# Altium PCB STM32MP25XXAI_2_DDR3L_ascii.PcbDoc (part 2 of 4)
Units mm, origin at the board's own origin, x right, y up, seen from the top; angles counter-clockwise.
Board outline 172 x 137 mm, 6 copper layers (Top Layer, Signal Layer 1, Signal Layer 2, Signal Layer 3, Signal Layer 4, Bottom Layer), stack 2.079 mm thick; 237 components, 152 nets, 1304 pads, 909 vias.
Unrouted connection lines stored in the file: 13.
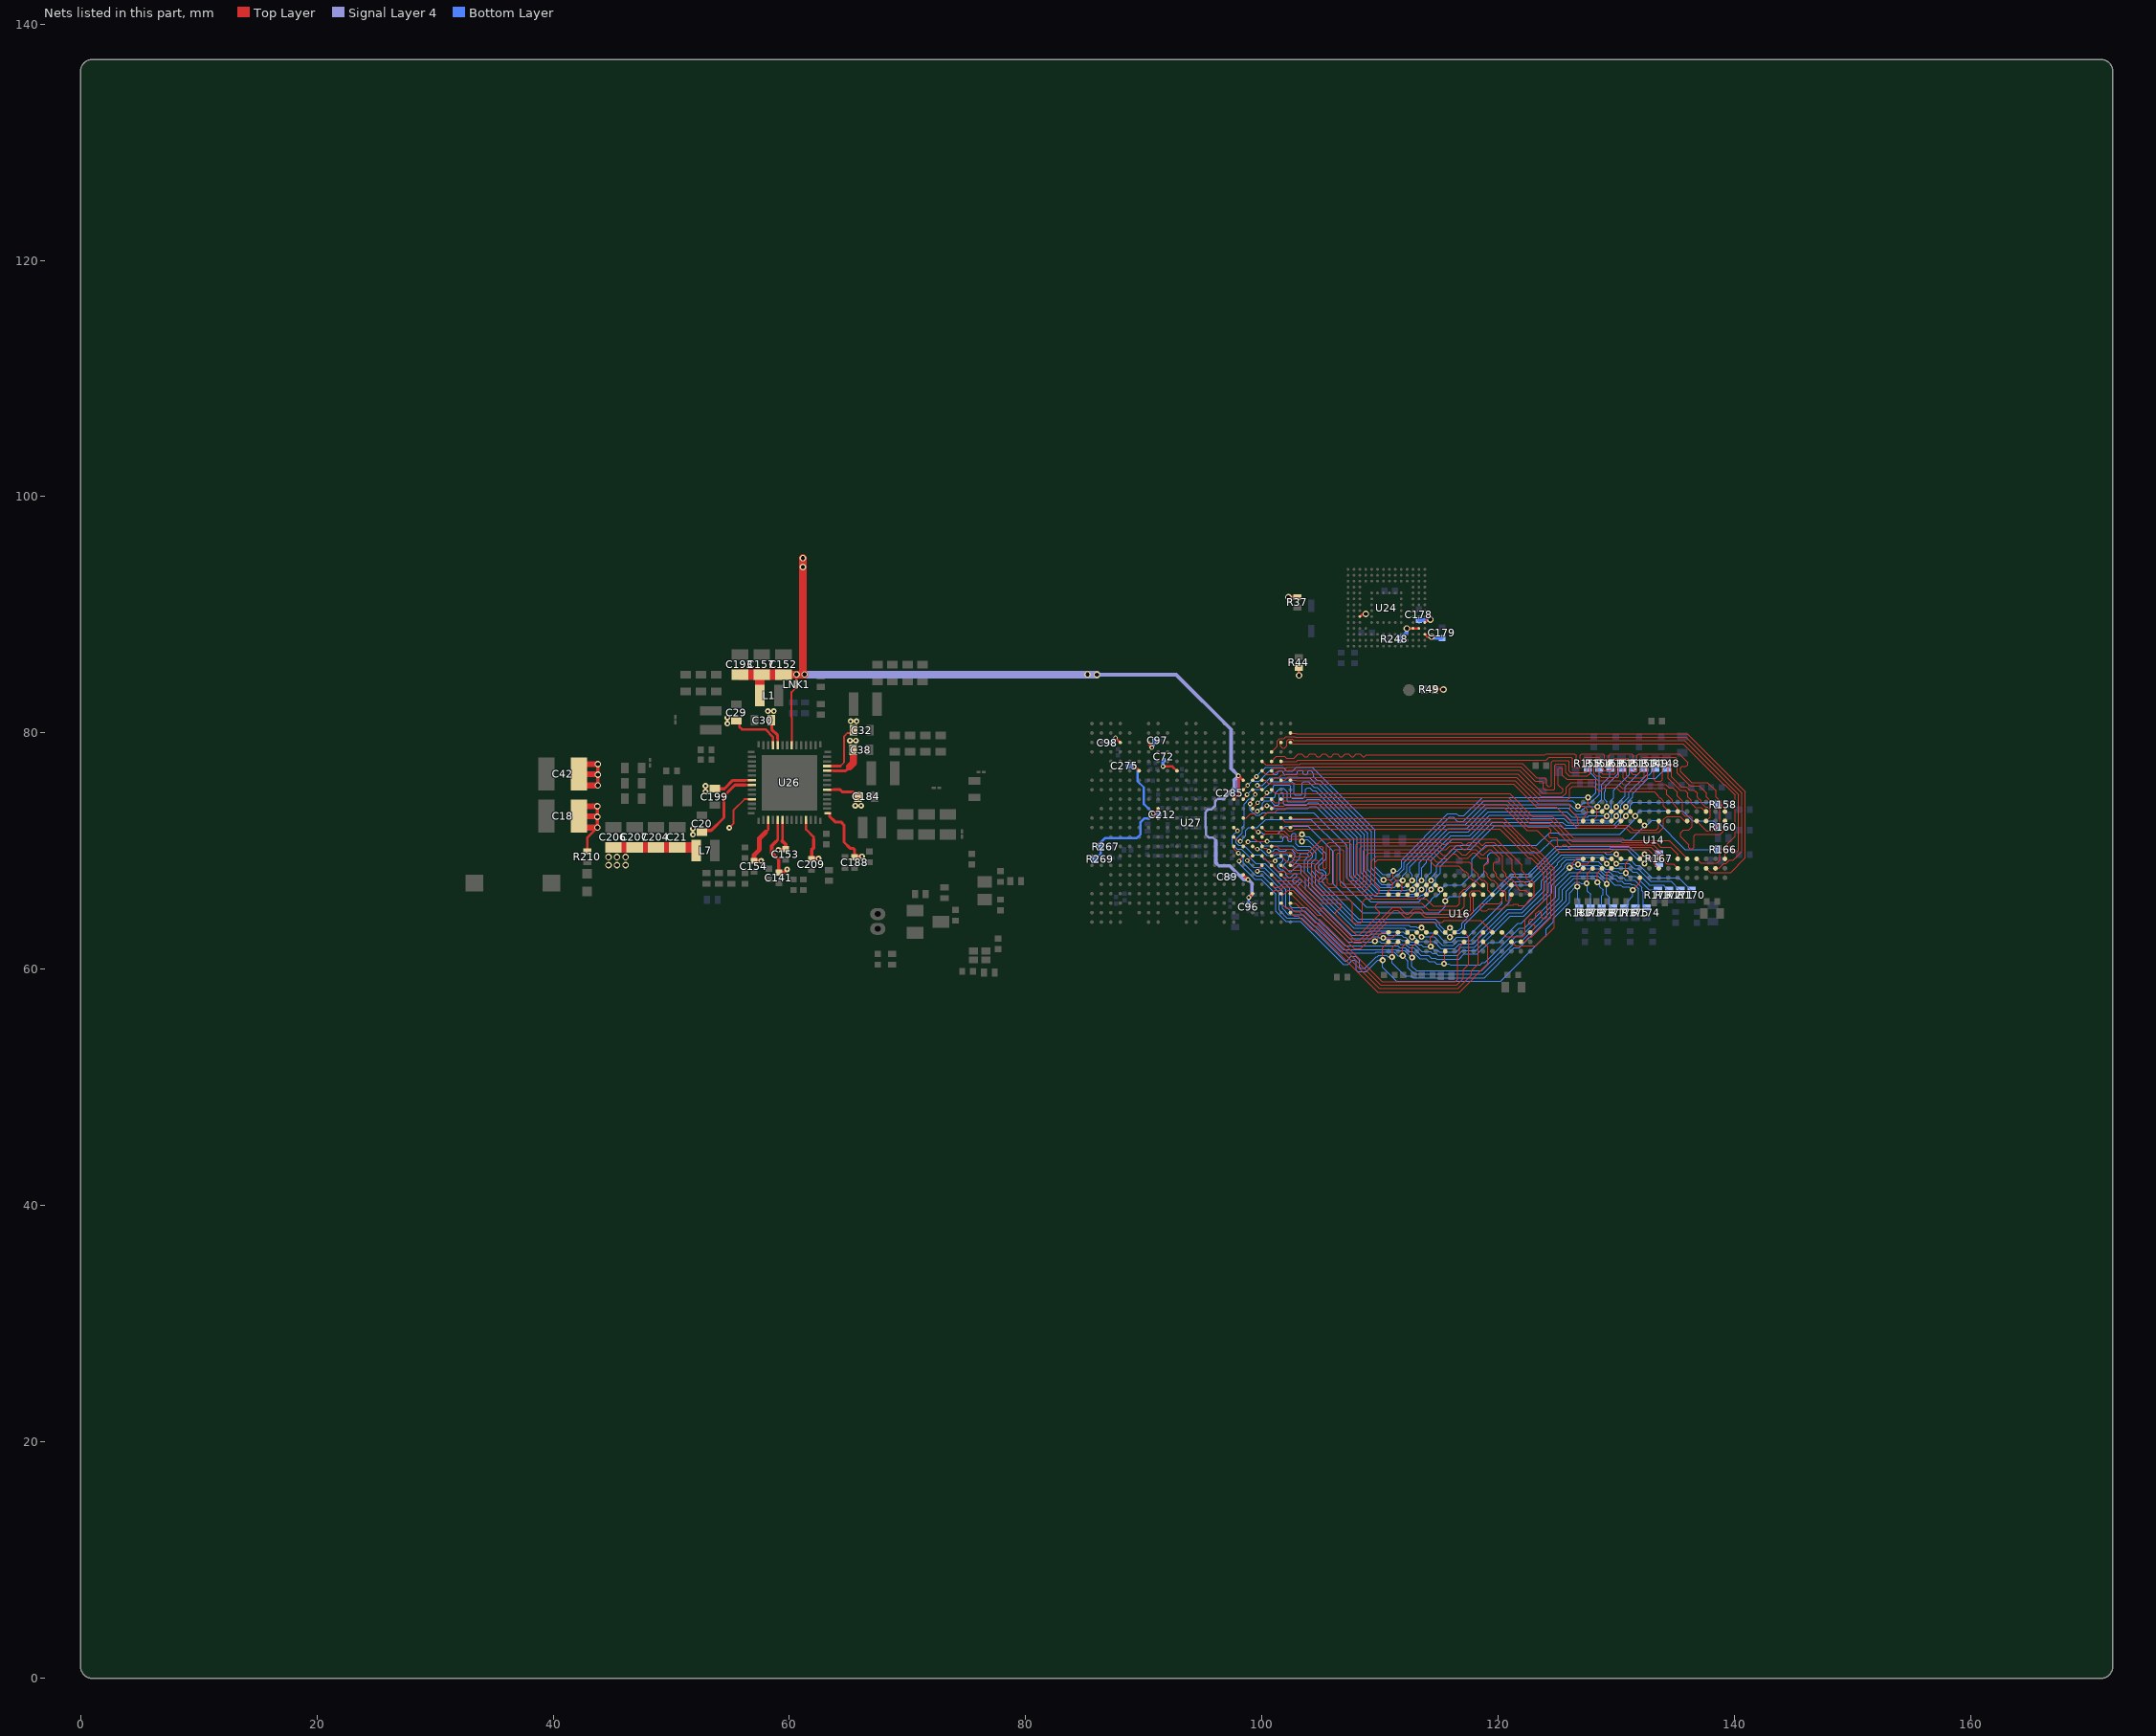
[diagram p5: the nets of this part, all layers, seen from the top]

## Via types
v1: diameter 0.55, hole 0.35, Top Layer to Bottom Layer, 421 vias
v2: diameter 0.4, hole 0.2, Top Layer to Bottom Layer, tented both sides, 169 vias
v3: diameter 0.5, hole 0.2, Top Layer to Bottom Layer, 146 vias
v4: diameter 0.5, hole 0.25, Top Layer to Bottom Layer, 145 vias
v5: diameter 0.4, hole 0.2, Top Layer to Bottom Layer, 28 vias

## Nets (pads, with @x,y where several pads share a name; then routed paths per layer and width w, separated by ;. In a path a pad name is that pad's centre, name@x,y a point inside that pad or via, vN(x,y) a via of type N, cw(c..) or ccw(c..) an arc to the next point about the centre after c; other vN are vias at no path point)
1V8: C72.2 C89.2 C96.2 C97.2 C98.2 C152.2 C157.2 C178.2 C179.2 C193.2 C212.2 C275.2 C285.2 L1.2 LNK1.2 R37.2 R44.2 R49.2 R248.2 R267.2 R269.1 U24.C6 U24.M4 U24.N4 U24.P3 U24.P5 U27.C4 U27.C7 U27.F6 U27.F10 U27.G17 U27.J16 U27.K8 U27.L8 U27.U17 U27.W18 | length 110.6
  Top Layer w0.2: LNK1.2@60.6,84.348 v1(60.6,84.95) ; v2(87.6,79.6) U27.C4@88,79.2 v2(87.6,79.6) ; v2(89.2,77.2) U27.F6@89.6,76.8 ; U27.C7@90.4,79.2 90.415,79.185 90.415,79.02 v2(90.66,78.775) ; U27.L8@91.2,72.8 91.175,72.8 v2(90.8,73.175) 91.2,73.575 U27.K8@91.2,73.6 ; v2(91.624,77.173) 92.413,77.173 92.786,76.8 U27.F10@92.8,76.8 ; U27.J16@97.6,74.4 98,74.8 v2(98,76.375) 98.012,76.375 98.388,76 U27.G17@98.4,76 ; U27.U17@98.4,68 v2(98.8,67.6) ; v2(98.868,66.067) U27.W18@99.2,66.4 ; v1(102.23,91.5) R37.2@102.975,91.5 ; R44.2@103.1,85.528 103.125,85.503 v1(103.125,84.875) ; U24.C6@108.275,89.85 108.452,90.027 108.727,90.027 v1(108.775,90.075) ; v1(112.25,88.85) U24.M4@112.775,88.85 U24.N4@113.275,88.85 ; U24.P3@113.775,88.35 113.975,88.15 v1(114.35,88.15) ; U24.P5@113.775,89.35 114.005,89.58 114.23,89.58 v1(114.25,89.6) ; R49.2@114.625,83.685 v1(115.35,83.685)
  Top Layer w0.64: C152.2@59.5,84.95 v1(60.6,84.95) v1(61.28,84.95) 61.142,85.088 v1(61.142,94.8)
  Top Layer w0.8: L1.2@57.495,83.175 57.495,84.9 57.545,84.95 C157.2@57.65,84.95
  Top Layer w0.9: C193.2@55.8,84.95 C157.2@57.545,84.95 ; C157.2@57.65,84.95 C152.2@59.5,84.95
  Signal Layer 4 w0.2: 96.075,70.9 95.825,71.15 95.484,71.15 95.399,71.235 95.248,71.386 95.248,72.063 95.201,72.109 95.201,73.292 95.317,73.408 95.317,73.433 95.434,73.55 95.723,73.55 96.007,73.834 96.007,74.166 96.003,74.169 96.257,74.423 96.684,74.423 ; v2(98.868,66.067) v2@98.868,66.094
  Signal Layer 4 w0.3: v1(86.019,84.939) 92.721,84.939 97.371,80.289 97.371,77.004 v2(98,76.375) ; 96.075,70.9 96.075,69.048 96.075,69.014 96.339,68.75 97.262,68.75 98.412,67.6 v2(98.8,67.6) ; 96.684,74.423 97.65,75.389 97.65,76.018 v2@98,76.367 ; v2(98.8,67.6) 99.15,67.25 99.15,66.377 v2@98.868,66.094
  Signal Layer 4 w0.64: v1@60.6,84.955 v1@61.28,84.955 ; v1(61.28,84.95) 86.009,84.95 v1(86.019,84.939)
  Bottom Layer w0.17: C89.2@97.35,67.825 97.415,67.89 97.44,67.89 97.56,68.01 98.39,68.01 v2(98.8,67.6)
  Bottom Layer w0.2: R269.1@85.854,69.315 85.854,69.41 86.009,69.565 86.104,69.565 86.35,69.811 R267.2@86.35,70.375 ; R267.2@86.325,70.715 86.697,71.087 89.377,71.087 89.723,71.434 89.723,72.448 90.059,72.783 90.457,72.783 90.8,73.127 v2(90.8,73.175) ; v2(89.2,77.2) 89.458,76.942 89.458,75.927 89.985,75.4 89.985,73.99 v2(90.8,73.175) ; v2(90.66,78.775) 90.66,78.79 90.825,78.955 C97.2@90.825,79.375 ; C212.2@91.31,73.1 91.272,73.138 90.837,73.138 v2(90.8,73.175) ; C96.2@98.85,65.55 98.85,66.05 v2(98.868,66.067)
  Bottom Layer w0.3: C98.2@87.175,79.175 v2(87.6,79.6) ; C72.2@91.6,77.7 91.6,77.224 91.624,77.2 v2(91.624,77.173) ; C285.2@97.555,74.91 97.94,75.295 97.94,76.288 98,76.348 v2(98,76.375) ; R248.2@111.675,87.95 112.241,88.516 112.241,88.841 v1(112.25,88.85) ; C178.2@113.275,89.55 114.132,89.55 114.182,89.6 v1(114.25,89.6) ; v1(114.35,88.15) 114.418,88.15 114.543,88.025 C179.2@115.225,88.025
  Bottom Layer w0.4: C275.2@88.675,77.2 v2(89.2,77.2)
  other v1: 85.224,84.95 61.131,94.047
1V8_FB: LNK1.1 U26.35 | length 5.1
  Top Layer w0.15: U26.35@60.2,78.97 60.2,81.311 60.175,81.336 60.175,83.473 LNK1.1@60.6,83.898
3V3: C21.2 C154.2 C204.2 C206.2 C207.2 L7.2 U26.3 U26.53 | length 15.3
  Top Layer w0.15: v3(54.91,71.977) 55.262,72.329 55.262,73.465 56.197,74.4 U26.53@56.83,74.4 ; U26.53@56.62,74.369 56.919,74.369 U26.53@56.95,74.4
  Top Layer w0.21: 57.973,71.598 58.2,71.825 U26.3@58.2,72.63
  Top Layer w0.3: C154.2@56.975,69.175 C154.2@57,69.175 v3@57.585,69.175
  Top Layer w0.4: C154.2@57,69.175 57.014,69.189 57.014,69.685 57.46,70.131 57.46,71.085 57.973,71.598
  Top Layer w0.9: C206.2@45.087,70.323 C21.2@50.5,70.323 51.862,70.323 L7.2@51.887,70.298
  other v1: 44.687,68.823 45.412,68.823 46.137,68.823 44.687,69.498 45.412,69.498 46.137,69.498
  other v3: 57.61,69.175
5V_STLK: C18.1 C20.2 C29.2 C30.2 C32.2 C38.2 C42.1 C153.2 C184.2 C188.2 C199.2 C209.2 R210.1 U26.6 U26.11 U26.15 U26.20 U26.24 U26.25 U26.38 U26.39 U26.49 U26.50 | length 56.5
  Top Layer w0.15: 64.3,77.2 64.625,77.525 64.625,79.731 64.888,79.994 65.319,79.994 C32.2@65.425,80.1
  Top Layer w0.2: R210.1@42.887,69.97 42.887,71.138 v1(43.751,72.002)
  Top Layer w0.21: C29.2@55.525,81.05 55.762,80.813 55.762,80.513 55.975,80.3 57.964,80.3 58.6,79.664 U26.39@58.6,78.97 ; 56.275,75.6 U26.50@56.83,75.6 ; 56.275,76 U26.49@56.83,76 ; U26.38@59,78.97 59,79.525 ; 59.4,70.85 U26.6@59.4,72.63 ; U26.11@61.4,72.63 61.4,71.843 62.04,71.203 62.04,70.975 ; U26.15@63.17,73.2 U26.15@63.245,73.2 U26.15@63.285,73.2 ; U26.20@63.17,75.2 63.725,75.2 ; U26.24@63.17,76.8 63.725,76.8 ; U26.25@63.17,77.2 64.3,77.2
  Top Layer w0.25: C20.2@52.6,71.75 53.375,71.75 54.45,72.825 54.45,74.669 55.381,75.6 56.275,75.6 ; C199.2@53.675,75.275 54.491,75.275 55.216,76 56.275,76 ; C30.2@58.425,81.075 58.494,81.006 58.494,80.308 59,79.802 59,79.525 ; 63.395,73.095 63.395,72.947 63.871,72.472 64.353,72.472 64.625,72.2 64.625,70.759 65.134,70.25 65.379,70.25 65.525,70.104 C188.2@65.525,69.55 ; 63.725,75.2 64.288,75.2 64.463,75.025 65.347,75.025 65.472,74.9 65.55,74.9 65.747,74.703 C184.2@65.747,74.625 ; 63.725,76.8 64.75,76.8 65.075,77.125
  Top Layer w0.3: v1(43.751,72.002) v1(43.751,72.902) v1(43.751,73.802) ; v1(43.776,75.565) v1(43.776,76.465) v1(43.776,77.365) ; v3(59.065,70.11) 59.675,70.11 59.674,70.111 59.674,70.576 59.4,70.85 ; C209.2@61.85,69.38 C209.2@61.875,69.38 ; 62.04,70.975 62.04,70.269 61.875,70.104 C209.2@61.875,69.38 ; v3(62.46,69.38) C209.2@61.875,69.38 ; C188.2@65.525,69.55 v3(66.135,69.55)
  Top Layer w0.5: C18.1@42.187,72.049 42.235,72.002 v1(43.751,72.002) ; C18.1@42.187,72.961 43.679,72.961 43.737,72.902 v1(43.751,72.902) ; C42.1@42.187,75.612 42.235,75.565 v1(43.776,75.565) ; C42.1@42.187,76.523 43.704,76.523 43.762,76.465 v1(43.776,76.465) ; C18.1@42.246,73.802 v1(43.751,73.802) ; C42.1@42.246,77.365 v1(43.776,77.365)
  Top Layer w0.6: 65.075,77.125 65.4,77.45 C38.2@65.4,78.175
  other v3: 51.825,71.4 51.825,71.9 65.575,73.85 66.075,73.85 52.9,75.025 52.9,75.525 65.125,79.35 65.625,79.35 54.75,80.8 65.175,81 65.675,81 54.75,81.3 58.175,81.85 58.675,81.85
5V_VCONN: C141.1 U26.5 | length 5.7
  Top Layer w0.21: 58.877,70.828 59,70.95 U26.5@59,72.63
  Top Layer w0.3: 58.877,70.828 58.51,70.46 58.51,69.865 59.1,69.275 C141.1@59.1,68.2 59.539,68.2 v3(59.8,68.46)
DDR_A0: R149.1 U14.N3 U16.N3 U27.L17 | length 50.4
  Top Layer w0.09: U27.L17@98.4,72.8 98.673,72.8 99.037,73.164 99.374,73.164 v5(99.6,73.39) ; U16.N3@113.101,66.327 113.101,66.376 v4@113.5,66.775 ; U14.N3@129.576,72.552 129.576,72.601 v4@129.975,73
  Bottom Layer w0.09: v5@99.603,73.39 100.016,73.803 100.016,74.043 100.219,74.246 100.712,74.246 101.058,73.9 101.348,73.9 101.443,73.995 101.443,74.811 101.603,74.971 101.748,74.971 101.833,74.886 101.833,74.017 101.95,73.9 103.774,73.9 103.962,74.088 104.682,74.088 105.043,73.727 ; 105.05,73.734 107.755,71.029 107.755,67.967 109.502,66.22 112.251,66.22 112.32,66.151 112.967,66.151 113.5,66.685 v4(113.5,66.745) 113.5,66.818 113.715,67.033 113.715,67.097 113.895,67.277 113.895,67.808 114.336,68.25 114.336,69.245 116.116,71.025 117.679,71.025 119.404,72.75 125.544,72.75 125.912,72.382 129.422,72.382 129.975,72.935 v4(129.975,72.97) v4@129.975,73 ; v4@129.976,73.013 129.976,73.139 130.37,73.534 130.37,73.908 131.064,74.602 131.064,74.979 132.537,76.452 132.751,76.452 132.971,76.672 132.971,76.767 133.181,76.977 R149.1@133.276,76.977
DDR_A1: R172.1 U14.P7 U16.P7 U27.P19 | length 48.6
  Top Layer w0.09: U27.P19@100.005,70.4 100.168,70.237 100.338,70.237 v5(100.575,70) ; U16.P7@112.301,63.127 v4(112.7,62.725) ; U14.P7@128.776,69.352 v4@129.176,68.952
  Bottom Layer w0.09: v5(100.575,70) 100.585,69.99 100.909,69.99 101.096,70.177 101.282,70.177 101.432,70.027 101.968,70.027 102.118,70.177 102.453,70.177 102.802,69.827 102.802,69.539 102.652,69.388 102.652,69.283 102.349,68.98 102.349,68.846 102.424,68.772 102.566,68.772 103.197,69.402 103.197,69.689 103.327,69.82 103.784,69.82 103.903,69.7 103.903,69.576 103.586,69.258 103.586,68.134 103.953,67.766 103.953,66.903 107.68,63.177 109.148,63.177 109.231,63.26 110.6,63.26 110.683,63.177 111.946,63.177 112.101,63.022 112.406,63.022 v4@112.672,62.756 ; v4@112.685,62.769 112.7,62.754 112.7,62.728 v4(112.7,62.725) 112.763,62.662 113.002,62.662 113.32,62.344 114.55,62.344 115.145,61.75 116.304,61.75 116.711,62.157 117.833,62.157 120.761,65.085 121.919,65.085 123.64,66.806 123.64,67.493 125.03,68.884 125.03,68.984 125.538,69.492 128.592,69.492 129.134,68.95 v4(129.175,68.95) 129.175,68.931 129.439,68.667 129.669,68.667 129.782,68.554 131.028,68.554 131.372,68.211 131.69,68.211 132.659,67.242 132.673,67.242 132.765,67.15 133.959,67.15 134.145,66.964 134.145,66.905 R172.1@134.45,66.6
DDR_A2: R151.1 U14.P3 U16.P3 U27.J19 | length 47.1
  Top Layer w0.09: U27.J19@100,74.4 100,74.438 100.341,74.779 100.341,74.891 v5(100.4,74.95) ; U16.P3@112.301,66.327 112.7,66.726 v4(112.7,66.745) ; U14.P3@128.776,72.552 129.175,72.951 v4(129.175,72.97)
  Bottom Layer w0.09: v5@100.403,74.95 100.747,74.95 100.95,75.153 100.95,75.501 101.051,75.602 102.305,75.602 102.413,75.494 102.413,74.594 102.527,74.48 103.461,74.48 103.689,74.708 103.689,75.224 103.824,75.359 104.044,75.359 104.287,75.115 104.517,75.115 108.355,71.278 108.355,68.187 109.842,66.7 112.213,66.7 112.258,66.745 v4(112.7,66.745) 112.778,66.823 112.778,67.042 113.095,67.358 113.095,67.845 113.168,67.918 113.168,67.92 113.3,68.052 113.3,69.057 ; 113.299,69.057 115.867,71.625 117.43,71.625 119.155,73.35 125.793,73.35 126.241,72.902 127.573,72.902 127.668,72.997 v4@129.172,72.997 ; v4(129.175,72.97) 129.175,73.095 129.57,73.49 129.57,74.31 129.765,74.505 129.765,75.167 131.071,76.472 131.071,76.767 131.281,76.977 R151.1@131.376,76.977
DDR_A3: R150.1 U14.N2 U16.N2 U27.K18 | length 47.8
  Top Layer w0.09: U27.K18@99.2,73.6 99.2,73.65 v5@99.625,74.075 ; U16.N2@113.101,67.127 113.476,67.502 v4@113.476,67.527 ; U14.N2@129.575,73.35 v4(129.975,73.75)
  Bottom Layer w0.09: v5@99.625,74.063 100.109,74.546 101.03,74.546 101.14,74.656 101.14,74.918 101.524,75.302 101.828,75.302 102.123,75.007 102.123,74.238 102.171,74.19 103.654,74.19 103.842,74.378 104.83,74.378 108.055,71.153 108.055,68.077 109.672,66.46 112.315,66.46 112.425,66.35 112.864,66.35 113.095,66.581 113.095,66.899 113.31,67.114 113.31,67.267 113.5,67.457 v4(113.5,67.525) 113.505,67.53 113.505,68.614 113.916,69.025 113.916,69.249 115.992,71.325 117.554,71.325 119.279,73.05 125.669,73.05 126.075,72.644 128.943,72.644 129.011,72.575 129.339,72.575 129.58,72.816 129.58,73.164 129.897,73.48 129.897,73.672 v4(129.975,73.75) ; v4@130.018,73.956 130.712,74.651 130.712,75.438 132.021,76.746 132.021,76.767 132.231,76.977 R150.1@132.326,76.977
  other v5: 99.625,74.1
DDR_A4: R178.1 U14.P8 U16.P8 U27.T19 | length 43.4
  Top Layer w0.09: v5(99.6,68.3) 99.6,68.302 99.798,68.501 99.798,68.591 U27.T19@100,68.793 ; v4(111.9,61.145) 111.901,61.927 U16.P8@112.301,62.327 ; v4(128.375,67.35) 128.376,68.152 U14.P8@128.776,68.552
  Bottom Layer w0.09: v5(99.6,68.3) 100.063,68.3 101.734,66.629 101.734,65.145 102.237,64.642 103.471,64.642 106.736,61.377 109.575,61.377 109.65,61.452 111.181,61.452 111.488,61.145 v4(111.9,61.145) 112.36,60.685 112.36,60.134 112.904,59.59 118.694,59.59 121.482,62.378 121.92,62.378 125.44,65.898 125.44,66.748 126.377,67.685 128.101,67.685 128.375,67.411 v4(128.375,67.35) 128.375,67.34 128.573,67.142 128.573,66.992 128.846,66.72 128.846,66.347 128.743,66.244 128.743,65.232 R178.1@128.75,65.225
DDR_A5: R152.1 U14.P2 U16.P2 U27.J17 | length 48.4
  Top Layer w0.09: U27.J17@98.4,74.4 98.4,74.438 98.725,74.763 v5(98.725,74.775) ; U16.P2@112.302,67.127 v4(112.7,67.525) ; U14.P2@128.776,73.352 128.777,73.352 v4(129.175,73.75)
  Bottom Layer w0.09: v5(98.725,74.775) 99.174,75.224 100.113,75.224 100.791,75.902 102.504,75.902 102.703,75.703 102.703,74.866 102.799,74.77 103.304,74.77 103.399,74.865 103.399,75.763 103.538,75.902 103.924,75.902 104.411,75.415 104.642,75.415 108.655,71.402 108.655,68.297 108.918,68.034 110.012,66.94 111.189,66.94 111.438,67.189 111.613,67.189 111.701,67.102 ; 111.699,67.1 111.859,66.94 112.029,66.94 112.216,67.127 112.302,67.127 v4(112.7,67.525) 112.7,68.005 112.487,68.218 112.487,68.669 115.743,71.925 117.306,71.925 119.031,73.65 125.917,73.65 126.425,73.142 127.3,73.142 127.503,73.345 128.644,73.345 129.049,73.75 v4(129.175,73.75) 129.191,73.766 129.191,74.172 128.972,74.391 128.972,75.001 129.076,75.105 129.076,75.477 130.121,76.522 130.121,76.767 130.331,76.977 R152.1@130.426,76.977
DDR_A6: R179.1 U14.R8 U16.R8 U27.P16 | length 46.7
  Top Layer w0.09: U27.P16@97.6,70.4 97.624,70.376 97.624,70.155 97.934,69.845 v5(98,69.845) ; v4(111,61.05) 111.047,61.096 111.047,61.872 U16.R8@111.5,62.325 ; v4(127.475,67.275) 127.523,67.323 127.523,68.09 127.976,68.542 U14.R8@127.976,68.552
  Bottom Layer w0.09: v5(98,69.845) 98.4,69.445 98.4,69.012 99.492,67.92 100.025,67.92 101.444,66.5 101.444,65.025 102.117,64.352 103.351,64.352 106.991,60.712 107.147,60.712 107.522,61.087 107.928,61.087 108.242,60.772 108.242,60.182 108.344,60.081 108.688,60.081 109.684,61.077 109.759,61.077 109.854,61.172 110.514,61.172 110.636,61.05 v4(111,61.05) 111,60.516 112.08,59.436 112.648,59.436 112.784,59.3 118.814,59.3 121.338,61.824 121.776,61.824 125.74,65.788 125.74,66.623 126.511,67.395 126.839,67.395 126.985,67.248 127.449,67.248 v4(127.475,67.275) 127.52,67.23 127.52,66.63 127.801,66.349 R179.1@127.801,65.227
DDR_A7: R155.1 U14.R2 U16.R2 U27.G18 | length 43.8
  Top Layer w0.09: U27.G18@99.2,76 v5(99.525,76.325) ; v4(111.1,68.325) 111.1,67.772 111.447,67.425 111.447,67.178 U16.R2@111.5,67.125 ; v4(127.575,74.55) 127.575,73.997 127.969,73.603 127.969,73.356 U14.R2@127.975,73.35
  Bottom Layer w0.09: v5(99.525,76.325) 100.302,77.102 101.791,77.102 102.111,76.782 102.594,76.782 102.914,77.102 104.228,77.102 109.555,71.775 109.555,68.67 110.187,68.038 110.81,68.038 111.097,68.325 v4(111.1,68.325) 111.505,68.325 111.8,68.62 111.8,69.255 115.72,73.175 116.432,73.175 116.616,72.991 117.099,72.991 118.658,74.55 v4(127.575,74.55) 127.615,74.59 127.9,74.59 128.249,74.938 128.249,76.156 127.767,76.638 127.767,76.786 R155.1@127.576,76.977
DDR_A8: R180.1 U14.T8 U16.T8 U27.R17 | length 45.9
  Top Layer w0.09: v5(98.05,69.15) 98.05,69.216 98.4,69.566 U27.R17@98.4,69.6 ; v4(110.2,60.775) 110.2,61.826 U16.T8@110.701,62.327 ; v4(126.675,67) 126.675,68.051 U14.T8@127.176,68.552
  Bottom Layer w0.09: v5@98.05,69.175 98.109,69.116 98.109,68.893 99.372,67.63 99.905,67.63 101.154,66.38 101.154,64.905 101.997,64.062 103.231,64.062 106.871,60.422 107.268,60.422 107.643,60.797 107.808,60.797 107.952,60.652 107.952,59.919 108.08,59.791 108.808,59.791 109.794,60.777 v4@110.2,60.777 ; v4(110.2,60.775) 110.2,60.189 111.379,59.01 120.203,59.01 124.063,62.871 124.063,63.411 124.67,64.017 124.67,64.308 126.03,65.668 126.03,66.458 126.571,67 v4(126.675,67) v4@126.675,66.903 ; v4@126.678,66.903 126.73,66.852 126.73,65.909 126.851,65.788 R180.1@126.851,65.227
DDR_A9: R153.1 U14.R3 U16.R3 U27.H19 | length 45.3
  Top Layer w0.09: v5(99.6,75.575) 99.625,75.575 U27.H19@100,75.2 ; U16.R3@111.501,66.327 111.876,66.702 v4@111.876,67.502 ; U14.R3@127.976,72.552 128.351,72.927 v4@128.351,73.727
  Bottom Layer w0.09: v5@99.605,75.57 100.038,75.57 100.67,76.202 104.049,76.202 104.536,75.715 104.766,75.715 108.955,71.526 108.955,68.421 109.88,67.496 109.88,67.404 110.104,67.18 111.005,67.18 111.351,67.526 v4@111.899,67.526 ; v4(111.9,67.525) 111.9,67.921 112.25,68.271 112.25,68.856 115.619,72.225 117.182,72.225 118.907,73.95 126.041,73.95 126.586,73.405 127.017,73.405 127.389,73.777 128.351,73.777 128.417,73.843 128.417,74.073 128.745,74.401 128.745,75.631 129.442,76.327 129.442,76.943 R153.1@129.476,76.977
  other v4: 128.375,73.75
DDR_A10: R173.1 U14.L7 U16.L7 U27.P18 | length 48.2
  Top Layer w0.09: U27.P18@99.2,70.4 99.254,70.4 99.42,70.234 99.541,70.234 v5(99.6,70.175) ; v4@114.256,61.931 114.256,62.681 U16.L7@114.7,63.125 ; v4(130.775,68.15) 130.775,68.95 U14.L7@131.175,69.35
  Bottom Layer w0.09: v5(99.6,70.175) 99.642,70.133 99.913,70.133 100.409,69.637 101.112,69.637 101.202,69.727 102.095,69.727 102.247,69.575 102.247,69.288 101.84,68.881 101.84,68.724 102.309,68.255 102.477,68.255 103.053,68.83 103.182,68.83 103.296,68.716 103.296,68.014 103.663,67.646 103.663,66.783 107.56,62.887 109.163,62.887 109.296,63.02 110.086,63.02 110.111,63.045 110.51,63.045 110.581,62.974 ; 110.582,62.974 110.679,62.877 111.822,62.877 111.977,62.722 112.14,62.722 112.52,62.342 112.524,62.342 112.536,62.33 113.013,62.33 113.266,62.077 113.47,62.077 113.623,61.924 v4@114.279,61.924 ; 115.024,61.46 115.013,61.46 114.833,61.64 114.561,61.64 114.561,61.644 v4(114.28,61.925) ; 115.024,61.46 116.424,61.46 116.831,61.867 117.968,61.867 120.886,64.785 122.029,64.785 123.94,66.696 123.94,67.369 125.33,68.759 125.33,68.874 125.726,69.27 126.921,69.27 127.081,69.109 128.45,69.109 129.082,68.477 129.496,68.477 129.667,68.305 129.862,68.305 129.913,68.254 130.13,68.254 130.234,68.15 v4(130.775,68.15) 130.775,68.125 131.025,67.875 131.615,67.875 132.741,66.75 R173.1@133.5,66.75 ; v4@114.279,61.924 v4(114.28,61.925)
DDR_A11: R174.1 U14.R7 U16.R7 U27.R19 | length 48.7
  Top Layer w0.09: U27.R19@100,69.6 100.42,69.18 v5(101.105,69.18) ; v4(110.25,62.65) 110.27,62.67 111.045,62.67 U16.R7@111.5,63.125 ; v4(126.725,68.875) 126.751,68.901 127.525,68.901 U14.R7@127.976,69.352
  Bottom Layer w0.09: v5(101.105,69.18) 101.105,69.206 101.326,69.427 101.686,69.427 101.769,69.344 101.769,69.22 101.331,68.782 101.331,68.672 101.585,68.418 101.736,68.418 102.012,68.142 102.012,67.992 102.25,67.754 102.393,67.754 102.762,68.123 102.876,68.123 102.961,68.038 102.961,67.903 102.596,67.538 102.596,67.408 102.693,67.31 102.83,67.31 103.147,67.628 103.271,67.628 103.366,67.533 103.366,67.409 103.047,67.09 103.047,66.956 107.406,62.597 109.212,62.597 109.368,62.753 109.37,62.753 109.386,62.77 109.822,62.77 109.943,62.649 v4(110.25,62.65) 110.3,62.65 v4@110.355,62.595 ; v4@110.401,62.577 111.698,62.577 111.853,62.422 112.143,62.422 112.506,62.059 112.947,62.059 113.501,61.505 114.254,61.505 114.409,61.35 114.713,61.35 114.893,61.17 114.904,61.17 116.544,61.17 116.951,61.577 118.102,61.577 121.02,64.495 122.149,64.495 124.24,66.586 124.24,67.245 125.63,68.635 125.63,68.764 125.861,68.995 126.247,68.995 126.365,68.877 126.826,68.877 126.893,68.809 128.445,68.809 129.028,68.227 129.425,68.227 129.71,67.942 130.006,67.942 130.204,67.745 130.587,67.745 130.773,67.559 131.521,67.559 132.154,66.926 132.154,66.636 132.249,66.541 132.249,65.437 132.459,65.227 R174.1@132.551,65.227
DDR_A12: R171.1 U14.N7 U16.N7 U27.P17 | length 48.9
  Top Layer w0.09: U27.P17@98.4,70.4 v5(98.8,70.8) ; U16.N7@113.101,63.127 113.101,63.102 v4@113.451,62.752 ; U14.N7@129.576,69.352 129.576,69.327 129.953,68.95 v4(129.975,68.95)
  Bottom Layer w0.09: v5@98.801,70.802 99.743,70.802 100.068,70.477 102.577,70.477 102.944,70.11 103.904,70.11 104.276,69.737 104.276,69.539 103.876,69.138 103.876,68.254 104.243,67.886 104.243,67.023 107.761,63.506 112.041,63.506 112.226,63.322 112.881,63.322 113.463,62.74 v4(113.5,62.74) ; v4@113.501,62.752 114.553,62.752 115.265,62.04 116.184,62.04 116.591,62.447 117.699,62.447 120.926,65.674 120.926,66.683 121.39,67.148 122.784,67.148 125.342,69.706 128.802,69.706 129.132,69.376 129.582,69.376 129.975,68.983 v4(129.975,68.95) 131.057,68.95 131.492,68.515 131.818,68.515 132.791,67.542 ; 132.794,67.545 132.889,67.45 134.605,67.45 135.305,66.75 R171.1@135.4,66.75 ; R171.1@135.352,66.703 R171.1@135.4,66.655
DDR_A13: R154.1 U14.T3 U16.T3 U27.H17 | length 48
  Top Layer w0.09: U27.H17@98.4,75.2 v5(98.775,75.575) ; v4(110.275,67.575) 110.775,67.575 111.05,67.3 111.05,66.95 110.701,66.601 U16.T3@110.701,66.327 ; v4@126.775,73.8 127.25,73.8 127.525,73.525 127.525,73.175 127.176,72.826 U14.T3@127.176,72.552
  Bottom Layer w0.09: v5(98.775,75.575) 99.127,75.927 99.739,75.927 100.624,76.812 100.816,76.812 100.932,76.696 100.932,76.57 101.011,76.492 101.24,76.492 101.317,76.569 101.317,76.701 101.429,76.812 101.671,76.812 101.767,76.716 101.767,76.606 101.881,76.492 102.887,76.492 103.006,76.612 103.006,76.727 103.091,76.812 103.389,76.812 103.474,76.727 103.474,76.587 103.559,76.502 103.778,76.502 103.863,76.587 103.863,76.717 103.948,76.802 104.103,76.802 104.378,76.528 104.378,76.297 104.66,76.015 104.89,76.015 109.255,71.65 109.255,68.546 110.226,67.575 v4(110.275,67.575) 110.976,67.575 111.369,67.968 111.482,67.968 112.025,68.512 112.025,69.055 115.845,72.875 116.175,72.875 116.525,72.525 117.057,72.525 118.782,74.25 126.275,74.25 126.725,73.8 v4(126.75,73.8) v4@126.775,73.8 ; v4@126.776,73.801 126.851,73.727 127.206,74.082 127.828,74.082 128.526,74.78 R154.1@128.526,76.977
DDR_A14: R175.1 U14.T7 U16.T7 U27.H18 | length 52.7
  Top Layer w0.09: U27.H18@99.2,75.2 99.2,75.145 99.366,74.979 99.366,74.859 v5(99.425,74.8) ; v4(109.55,62.375) 109.574,62.375 109.847,62.648 109.847,62.825 110.149,63.127 U16.T7@110.701,63.127 ; v4(126.025,68.6) 126.084,68.6 126.33,68.846 126.33,69.039 126.643,69.352 U14.T7@127.176,69.352
  Bottom Layer w0.09: v5(99.425,74.8) 99.033,74.408 98.907,74.408 98.474,73.975 98.474,72.194 98.319,72.04 98.319,71.552 97.805,71.038 97.805,70.682 98.007,70.48 98.469,70.48 99.279,69.67 99.804,69.67 100.137,69.337 100.257,69.337 107.286,62.307 109.482,62.307 v4(109.55,62.375) ; v4@109.551,62.377 109.964,62.377 110.086,62.255 111.596,62.255 111.729,62.122 112.146,62.122 112.456,61.812 112.813,61.812 113.427,61.198 114.078,61.198 114.316,60.96 114.684,60.96 114.764,60.88 116.664,60.88 117.071,61.287 118.222,61.287 119.209,62.274 120.038,62.274 121.659,63.894 121.959,63.894 124.54,66.475 124.54,67.12 126.019,68.6 v4(126.025,68.6) 126.441,68.6 126.561,68.48 126.914,68.48 126.943,68.509 128.443,68.509 128.965,67.987 129.325,67.987 129.667,67.645 129.879,67.645 130.079,67.445 130.463,67.445 130.649,67.259 131.177,67.259 131.242,67.195 131.461,67.195 131.526,67.13 131.528,67.13 131.854,66.804 131.854,65.435 131.644,65.225 R175.1@131.6,65.225
DDR_A15: R170.1 U14.M7 U16.M7 U27.N18 | length 50.9
  Top Layer w0.09: U27.N18@99.2,71.2 99.575,70.825 v5(100.425,70.825) ; v4(113.501,63.527) U16.M7@113.9,63.127 ; v4(129.975,69.745) 129.978,69.745 U14.M7@130.371,69.352 ; U14.M7@130.373,69.35 U14.M7@130.375,69.35
  Bottom Layer w0.09: v5(100.425,70.825) 101.679,70.827 101.775,70.923 101.775,71.086 101.944,71.254 102.069,71.254 102.175,71.149 102.175,70.91 102.258,70.827 102.451,70.827 102.499,70.875 102.499,71.407 102.612,71.52 102.762,71.52 102.864,71.419 102.864,70.615 103.078,70.4 104.024,70.4 104.566,69.857 104.566,69.419 104.186,69.038 104.186,68.354 104.533,68.006 104.533,67.144 107.931,63.746 112.425,63.746 112.548,63.623 113.027,63.623 113.124,63.526 113.499,63.526 v4(113.501,63.527) 113.957,63.071 114.723,63.071 115.463,62.33 116.064,62.33 116.471,62.737 117.421,62.737 120.302,65.618 120.302,66.469 121.27,67.438 122.664,67.438 125.172,69.946 128.925,69.946 129.146,69.725 129.975,69.725 129.975,69.648 130.345,69.279 131.152,69.279 131.616,68.815 131.951,68.815 133.011,67.755 135.25,67.755 R170.1@136.35,66.655
DDR_BA0: R148.1 U14.M2 U16.M2 U27.K19 | length 46.9
  Top Layer w0.09: U27.K19@100,73.6 100.054,73.6 100.245,73.791 100.341,73.791 v5(100.4,73.85) ; U16.M2@113.901,67.127 113.913,67.127 114.3,67.514 v4(114.3,67.525) ; U14.M2@130.376,73.352 130.388,73.352 130.775,73.739 v4(130.775,73.75)
  Bottom Layer w0.09: v5(100.4,73.85) 100.696,73.852 100.938,73.61 103.894,73.61 104.082,73.798 104.562,73.798 107.455,70.905 107.455,67.857 109.332,65.98 112.187,65.98 112.223,65.944 113.128,65.944 113.458,66.274 113.614,66.274 113.905,66.564 113.905,66.909 114.085,67.089 114.085,67.247 114.3,67.462 v4(114.3,67.525) 114.35,67.575 114.35,67.839 114.762,68.252 114.762,68.782 116.463,70.483 117.561,70.483 119.528,72.45 125.42,72.45 125.688,72.182 129.753,72.182 130.375,72.804 130.375,73.25 v4@130.835,73.71 ; v4(130.775,73.75) 130.775,73.835 130.974,74.034 130.974,74.182 131.364,74.571 131.364,74.855 132.661,76.152 133.306,76.152 134.131,76.977 R148.1@134.226,76.977
DDR_BA1: R177.1 U14.N8 U16.N8 U27.R18 | length 45.6
  Top Layer w0.09: v5(98.75,69.2) 98.775,69.2 99.175,69.6 U27.R18@99.2,69.6 ; v4(112.7,61) 112.7,61.926 U16.N8@113.101,62.327 ; v4(129.175,67.225) 129.175,68.151 U14.N8@129.576,68.552
  Bottom Layer w0.09: v5(98.75,69.2) 98.75,69.157 99.253,68.654 99.798,68.654 99.863,68.59 100.183,68.59 102.034,66.739 102.034,65.269 102.361,64.942 103.595,64.942 106.86,61.677 111.325,61.677 111.414,61.588 112.065,61.588 112.653,61 v4(112.7,61) 112.68,60.98 112.68,60.269 113.07,59.88 118.574,59.88 121.545,62.85 121.982,62.85 125.14,66.008 125.14,66.872 126.183,67.915 128.424,67.915 129.011,67.329 129.071,67.329 v4(129.175,67.225) 129.153,67.203 129.153,66.319 129.396,66.077 129.396,65.437 129.606,65.227 R177.1@129.701,65.227
DDR_BA2: R158.1 U14.M3 U16.M3 U27.J18 | length 51.7
  Top Layer w0.09: v5(98.99,74) 99.05,74.059 99.05,74.193 99.2,74.343 U27.J18@99.2,74.4 ; U16.M3@113.901,66.327 113.901,66.365 v4@114.3,66.764 ; U14.M3@130.376,72.552 130.376,72.59 v4@130.775,72.989
  Bottom Layer w0.09: v5(98.99,74) 98.99,73.512 99.457,73.045 99.789,73.045 100.014,73.27 104.378,73.27 107.155,70.493 107.155,67.746 109.166,65.735 113.273,65.735 113.534,65.996 113.653,65.996 114.3,66.643 v4(114.3,66.745) 114.3,66.866 114.498,67.063 114.498,67.164 114.696,67.362 114.696,67.76 115.1,68.165 115.1,68.709 116.573,70.183 117.685,70.183 119.652,72.15 125.275,72.15 125.483,71.942 129.854,71.942 130.726,72.814 130.726,73.041 131.17,73.485 131.17,73.904 131.426,74.16 138.365,74.16 R158.1@138.575,73.95
  other v4: 130.775,72.97
DDR_CASN: R166.1 U14.K3 U16.K3 U27.M18 | length 50.8
  Top Layer w0.09: U27.M18@99.2,72 99.22,72 99.595,71.625 v5(99.675,71.625) ; v4(115.5,65.775) U16.K3@115.501,66.327 ; U14.K3@131.975,72.55 132,72.55 v4@132.377,72.172
  Bottom Layer w0.09: v5(99.675,71.625) 99.72,71.583 99.964,71.583 100.066,71.481 101.336,71.481 101.965,72.11 103.898,72.11 105.995,70.013 105.995,67.266 108.486,64.775 114.967,64.775 115.5,65.308 v4(115.5,65.775) 115.87,66.145 116.796,66.145 118.78,68.13 118.78,68.778 119.116,69.114 119.116,69.658 119.338,69.88 123.494,69.88 124.561,70.947 131.152,70.947 v4(132.375,72.17) 132.486,72.17 132.6,72.284 132.683,72.284 132.994,72.595 133.339,72.595 135.784,70.15 R166.1@138.575,70.15
DDR_CKE: R176.1 U14.K9 U16.K9 U27.M16 | length 49.3
  Top Layer w0.09: U27.M16@97.6,72 97.625,72 97.9,71.725 v5(97.925,71.725) ; v4(115.4,60.475) 115.445,60.52 115.445,61.472 U16.K9@115.501,61.527 ; v4(131.375,66.725) 131.976,67.326 U14.K9@131.976,67.752
  Bottom Layer w0.09: v5(97.925,71.725) 97.495,71.295 97.495,70.574 97.879,70.19 98.249,70.19 99.474,68.964 100.219,68.964 102.334,66.849 102.334,65.393 102.485,65.242 103.719,65.242 106.985,61.977 111.491,61.977 111.633,61.835 112.114,61.835 112.423,61.527 112.732,61.527 113.339,60.92 113.864,60.92 114.114,60.67 114.564,60.67 114.758,60.476 v4@115.399,60.476 ; v4@115.404,60.471 115.836,60.471 115.945,60.363 118.447,60.363 118.664,60.58 118.864,60.58 121.774,63.49 122.212,63.49 124.84,66.118 124.84,66.996 126.049,68.205 128.442,68.205 128.95,67.697 129.268,67.697 129.82,67.145 130.339,67.145 130.525,66.959 131.053,66.959 131.287,66.725 v4(131.375,66.725) 131.375,66.2 130.955,65.78 130.955,65.435 130.745,65.225 R176.1@130.65,65.225
DDR_CLK_N: R167.2 U14.K7 U16.K7 U27.M19 | length 45.3
  Top Layer w0.09: U27.M19@100,72 100.285,71.715 101.842,71.715 102.293,71.264 103.124,71.264 103.285,71.425 v4(103.381,71.425) ; U16.K7@115.501,63.127 v4(115.9,63.525) ; U14.K7@131.977,69.352 v4@132.375,69.75
  Bottom Layer w0.09: v4@103.381,71.417 103.5,71.417 103.671,71.246 103.941,71.246 105.415,69.772 105.415,69.375 104.753,68.712 104.753,68.588 104.888,68.452 105.13,68.452 105.415,68.167 105.415,67.829 105.073,67.487 105.073,67.367 108.171,64.27 114.632,64.27 115.012,63.891 115.012,63.744 115.488,63.268 115.641,63.268 v4(115.9,63.525) 116.151,63.277 116.651,63.277 116.925,63.551 116.925,63.912 121.093,68.08 122.542,68.08 124.898,70.436 131.001,70.436 131.93,69.507 132.14,69.507 v4@132.375,69.742 ; v4(132.375,69.745) 132.629,69.491 133.173,69.491 133.296,69.614 133.296,69.617 133.506,69.827 R167.2@133.601,69.827
DDR_CLK_P: R167.1 U14.J7 U16.J7 U27.N19 | length 45.4
  Top Layer w0.09: U27.N19@100,71.2 100.009,71.2 100.294,71.485 101.718,71.485 102.189,71.014 103.124,71.014 103.313,70.825 v4(103.381,70.825) ; v4(115.9,62.725) U16.J7@116.3,63.125 ; v4@132.375,68.95 U14.J7@132.775,69.35
  Bottom Layer w0.09: v4(103.381,70.825) 103.492,70.825 103.664,70.996 103.837,70.996 105.165,69.669 105.165,69.478 104.503,68.816 104.503,68.485 104.785,68.202 105.026,68.202 105.165,68.064 105.165,67.932 104.823,67.591 104.823,67.264 108.067,64.02 114.529,64.02 114.762,63.787 114.762,63.64 115.384,63.018 115.63,63.018 115.901,62.747 v4(115.9,62.725) 116.201,63.027 116.754,63.027 117.175,63.448 117.175,63.809 121.196,67.83 122.646,67.83 125.002,70.186 130.898,70.186 131.827,69.257 132.068,69.257 v4@132.375,68.95 ; v4(132.375,68.955) 132.661,69.241 133.19,69.241 133.294,69.137 133.391,69.137 R167.1@133.6,68.925
DDR_CSN: R160.1 U14.L2 U16.L2 U27.N16 | length 53.1
  Top Layer w0.09: U27.N16@97.6,71.2 97.916,70.884 98.091,70.884 v5(98.15,70.825) ; U16.L2@114.7,67.125 114.716,67.125 v4@115.096,66.745 ; U14.L2@131.175,73.35 131.191,73.35 131.571,72.97 v4(131.575,72.97)
  Bottom Layer w0.09: v5(98.15,70.825) 98.626,71.301 98.626,71.748 98.857,71.979 99.593,71.979 100.304,72.69 104.138,72.69 106.575,70.253 106.575,67.506 108.819,65.262 113.746,65.262 114.337,65.853 114.337,65.92 114.568,66.152 114.783,66.152 115.063,66.431 115.063,66.708 v4(115.1,66.745) ; v4@115.1,66.75 115.5,67.15 116.864,67.15 117.752,68.038 117.752,69.31 118.929,70.487 123.252,70.487 124.312,71.547 125.044,71.547 125.157,71.434 130.276,71.434 131.503,72.661 131.503,72.898 v4(131.575,72.97) ; v4@131.575,72.976 132,73.402 135.596,73.402 136.452,72.546 138.188,72.546 138.378,72.355 R160.1@138.582,72.056
DDR_DQ0: U16.H8 U27.W22 | length 20.7
  Top Layer w0.09: U27.W22@102.401,66.377 102.476,66.377 104.608,64.246 104.85,64.246 110.14,58.955 116.34,58.955 116.562,59.176 116.562,61.228 116.7,61.366 116.7,61.925 U16.H8@117.1,62.325
DDR_DQ1: U16.F7 U27.Y21 | length 23.6
  Top Layer w0.09: U27.Y21@101.6,65.6 102.003,65.2 102.427,65.2 102.774,64.853 103.152,64.853 104.359,63.646 104.629,63.646 109.9,58.375 116.581,58.375 117.746,59.54 117.746,59.897 118.302,60.453 118.302,62.726 U16.F7@118.7,63.125
DDR_DQ2: U16.H7 U27.Y22 | length 22
  Top Layer w0.09: U27.Y22@102.4,65.6 102.833,65.6 104.497,63.936 104.75,63.936 110.02,58.665 116.46,58.665 117.054,59.258 117.054,59.979 117.497,60.422 117.497,62.724 U16.H7@117.1,63.122
DDR_DQ3: U16.F8 U27.AA22 | length 22.5
  Top Layer w0.09: U27.AA22@102.4,64.8 102.688,64.515 103.066,64.515 104.235,63.346 104.519,63.346 109.78,58.085 116.701,58.085 119.097,60.482 119.097,61.928 U16.F8@118.7,62.325
DDR_DQ4: U16.E3 U27.T21 | length 23.1
  Top Layer w0.09: U27.T21@101.601,68.802 101.791,68.612 101.933,68.612 102.16,68.385 103.367,68.385 105.175,66.577 108.611,66.577 109.242,67.208 109.242,69.141 109.661,69.56 114.304,69.56 114.787,69.077 117.521,69.077 117.75,68.848 117.75,68.548 118.028,68.27 118.043,68.27 118.285,68.028 118.285,67.848 118.589,67.543 118.779,67.543 119.118,67.205 119.118,66.71 U16.E3@119.501,66.327
DDR_DQ5: U16.F2 U27.T20 | length 23.2
  Top Layer w0.09: U27.T20@100.801,68.802 100.826,68.802 101.316,68.312 101.823,68.312 102.04,68.095 103.233,68.095 105.051,66.277 109.708,66.277 109.91,66.478 109.91,66.808 109.532,67.186 109.532,69.021 109.781,69.27 114.13,69.27 114.623,68.777 116.623,68.777 117.13,68.27 117.243,68.27 117.457,68.056 117.457,67.876 117.806,67.527 118.002,67.527 118.402,67.127 U16.F2@118.701,67.127
DDR_DQ6: U16.G2 U27.U21 | length 22.2
  Top Layer w0.09: U27.U21@101.6,68 101.634,68 101.829,67.805 103.099,67.805 105.001,65.903 107.366,65.903 107.631,65.637 107.631,64.047 107.77,63.908 108.293,63.908 108.476,64.091 108.476,65.693 108.749,65.967 113.871,65.967 114.483,65.355 116.511,65.355 116.697,65.542 116.697,66.41 117.067,66.78 117.243,66.78 117.587,67.124 U16.G2@117.9,67.125 U16.G2@117.9,67.125
DDR_DQ7: U16.H3 U27.U20 | length 22.9
  Top Layer w0.09: U27.U20@100.8,68 101.285,67.515 102.965,67.515 104.878,65.602 106.563,65.602 106.703,65.462 106.703,65.275 106.237,64.809 106.237,64.644 107.95,62.931 108.233,62.931 109.969,64.666 109.969,64.835 109.631,65.172 109.631,65.432 109.801,65.602 113.522,65.602 114.087,65.037 116.836,65.037 117.101,65.301 U16.H3@117.101,66.327
DDR_DQ8: U16.D7 U27.M21 | length 32.1
  Top Layer w0.09: U27.M21@101.601,72.002 101.976,72.002 102.276,71.702 102.601,71.702 102.769,71.871 120.126,71.871 122.561,69.435 122.762,69.435 123.31,68.887 123.31,68.686 123.85,68.146 123.85,65.802 122.243,64.195 122.243,62.971 122.052,62.78 120.645,62.78 U16.D7@120.3,63.125
DDR_DQ9: U16.A7 U27.M22 | length 31.6
  Top Layer w0.09: U27.M22@102.401,72.002 102.586,72.187 120.219,72.187 122.681,69.725 122.882,69.725 123.6,69.007 123.6,68.807 124.14,68.267 124.14,64.484 123.965,64.309 123.765,64.309 123.657,64.416 123.657,64.861 123.572,64.946 123.419,64.946 123.171,64.698 123.171,64.403 123.016,64.248 122.72,64.248 122.59,64.118 122.59,63.894 122.666,63.818 122.971,63.818 123.129,63.66 123.129,63.522 122.732,63.125 U16.A7@122.7,63.125
DDR_DQ10: U16.B8 U27.L21 | length 32.2
  Top Layer w0.09: U27.L21@101.6,72.8 101.613,72.8 101.936,72.477 120.34,72.477 122.802,70.015 123.003,70.015 123.89,69.128 123.89,68.927 124.43,68.387 124.43,64.364 122.791,62.725 122.605,62.725 122.205,62.325 U16.B8@121.9,62.325
DDR_DQ11: U16.C8 U27.L22 | length 33.6
  Top Layer w0.09: U27.L22@102.401,72.802 102.436,72.767 120.46,72.767 122.922,70.305 123.123,70.305 124.18,69.248 124.18,69.047 124.72,68.507 124.72,63.534 123.166,61.98 121.445,61.98 U16.C8@121.1,62.325
DDR_DQ12: U16.C3 U27.T22 | length 32.8
  Top Layer w0.09: U27.T22@102.4,68.8 102.457,68.8 102.582,68.675 104.107,68.675 104.22,68.562 104.22,67.971 104.767,67.424 105.149,67.424 105.264,67.309 105.264,67.185 105.534,66.915 106.177,66.915 106.34,67.078 106.34,69.772 106.425,69.857 106.551,69.857 106.636,69.772 106.636,67.102 106.817,66.92 108.475,66.92 108.866,67.311 108.866,69.639 109.076,69.85 114.564,69.85 115.037,69.377 115.76,69.377 116.139,69.756 116.364,69.756 116.733,69.387 117.397,69.387 117.86,69.85 117.992,69.85 118.451,69.391 119.086,69.391 119.192,69.285 119.192,69.045 119.068,68.92 118.928,68.92 118.78,68.772 118.78,68.336 119.045,68.071 119.045,67.86 119.37,67.535 119.609,67.535 119.955,67.188 119.955,66.982 120.254,66.683 120.448,66.683 120.645,66.486 120.645,65.852 120.745,65.752 120.921,65.752 121.078,65.909 121.078,66.303 U16.C3@121.1,66.325
DDR_DQ13: U16.A2 U27.R20 | length 34.5
  Top Layer w0.09: U27.R20@100.801,69.602 100.809,69.602 101.092,69.885 102.518,69.885 102.858,69.545 104.013,69.545 104.903,70.436 105.042,70.436 105.168,70.31 105.168,68.589 105.253,68.504 105.385,68.504 105.47,68.589 105.47,70.533 105.674,70.737 107.366,70.737 107.557,70.545 107.557,67.9 107.657,67.8 107.803,67.8 107.976,67.973 107.976,70.543 108.184,70.751 115.092,70.751 115.27,70.573 115.544,70.573 115.722,70.751 116.844,70.751 117.043,70.552 117.278,70.552 117.476,70.751 118.334,70.751 118.572,70.512 118.692,70.512 118.931,70.751 119.647,70.751 121.175,69.223 121.175,68.338 121.461,68.052 121.461,67.872 121.862,67.47 122.091,67.47 122.377,67.184 122.641,67.184 U16.A2@122.7,67.125
DDR_DQ14: U16.C2 U27.R21 | length 33.5
  Top Layer w0.09: U27.R21@101.6,69.6 101.6,69.595 102.1,69.095 102.572,69.095 102.702,68.965 104.393,68.965 104.51,68.847 104.51,68.091 104.887,67.714 105.454,67.714 105.554,67.613 105.554,67.305 105.655,67.205 105.911,67.205 106.05,67.344 106.05,70.008 106.189,70.147 106.801,70.147 106.926,70.022 106.926,67.299 107.014,67.21 108.355,67.21 108.576,67.431 108.576,70.036 108.679,70.14 114.811,70.14 115.284,69.667 115.562,69.667 116.066,70.171 116.409,70.171 116.903,69.677 117.277,69.677 117.74,70.14 118.112,70.14 118.571,69.681 118.743,69.681 119.212,70.15 119.364,70.15 120.081,69.433 120.081,69.178 119.964,69.062 119.687,69.062 119.575,68.95 119.575,68.341 119.845,68.071 119.845,67.855 120.148,67.552 120.447,67.552 120.825,67.174 121.054,67.174 U16.C2@121.101,67.127
DDR_DQ15: U16.A3 U27.R22 | length 32.7
  Top Layer w0.09: U27.R22@102.4,69.6 102.743,69.255 104.644,69.255 104.8,69.099 104.8,68.211 105.007,68.004 105.585,68.004 105.76,68.179 105.76,70.328 105.878,70.447 107.045,70.447 107.226,70.266 107.226,67.646 107.371,67.5 108.088,67.5 108.276,67.688 108.276,70.247 108.489,70.461 114.934,70.461 115.266,70.129 115.567,70.129 115.899,70.461 116.724,70.461 117.049,70.136 117.279,70.136 117.596,70.453 117.596,70.461 118.201,70.461 118.545,70.117 118.707,70.117 119.051,70.461 119.463,70.461 120.371,69.553 120.371,68.34 120.372,68.34 120.66,68.053 120.66,67.873 120.956,67.577 121.158,67.577 121.493,67.241 121.493,67.036 121.819,66.71 122.317,66.71 U16.A3@122.701,66.327
DDR_DQ16: U14.B8 U27.D20 | length 50.3
  Top Layer w0.09: U27.D20@100.801,78.402 101.294,78.895 101.294,79.322 101.489,79.517 101.825,79.517 101.837,79.517 102.011,79.692 102.746,79.692 102.786,79.652 135.868,79.652 140.615,74.906 140.615,69.983 139.886,69.255 139.568,69.255 139.263,68.95 139.049,68.95 138.649,68.55 U14.B8@138.375,68.55
DDR_DQ17: U14.D7 U27.C22 | length 47.7
  Top Layer w0.09: U27.C22@102.4,79.2 102.417,79.2 102.545,79.072 135.628,79.072 139.055,75.645 139.143,75.645 140.035,74.753 140.035,71.275 138.747,69.988 138.747,69.234 138.518,69.005 137.123,69.005 U14.D7@136.776,69.352
DDR_DQ18: U14.A7 U27.C21 | length 48.9
  Top Layer w0.09: U27.C21@101.6,79.2 101.584,79.184 101.584,78.875 101.734,78.725 101.9,78.725 102.105,78.93 102.105,79.322 102.278,79.495 102.533,79.495 102.666,79.362 135.748,79.362 140.325,74.785 140.325,70.103 140.053,69.831 139.933,69.831 139.848,69.916 139.848,70.372 139.755,70.465 139.634,70.465 139.179,70.01 U14.A7@139.179,69.354
DDR_DQ19: U14.C8 U27.B22 | length 50.1
  Top Layer w0.09: U27.B22@102.4,80 102.418,79.982 102.866,79.982 102.906,79.942 135.988,79.942 140.905,75.026 140.905,69.451 139.659,68.205 137.92,68.205 U14.C8@137.575,68.55
DDR_DQ20: U14.C2 U27.F20 | length 50.8
  Top Layer w0.09: U27.F20@100.801,76.802 101.001,77.002 101.805,77.002 101.855,77.052 102.1,77.052 102.15,77.102 103.348,77.102 103.378,77.132 121.899,77.132 123.116,75.915 123.695,75.915 123.81,75.8 123.81,75.307 123.913,75.204 124.701,75.204 124.786,75.289 124.786,77.259 124.889,77.362 125.584,77.362 125.711,77.235 125.711,76.663 126.008,76.365 127.547,76.365 127.77,76.588 127.77,77.165 127.855,77.25 128.018,77.25 128.103,77.165 128.103,76.548 128.286,76.365 128.589,76.365 128.714,76.24 130.107,76.24 130.22,76.353 130.22,77.194 130.315,77.289 130.468,77.289 130.553,77.204 130.553,76.202 130.828,75.928 132.323,75.928 132.62,76.224 132.62,77.213 132.779,77.372 132.991,77.372 133.15,77.213 133.15,76.069 133.292,75.928 133.749,75.928 133.884,76.062 133.884,77.282 133.974,77.372 134.27,77.372 134.372,77.271 134.372,76.176 135.389,75.159 135.776,75.159 136.023,74.912 136.023,74.589 136.05,74.563 136.118,74.495 136.322,74.29 136.322,74.052 136.672,73.702 137.163,73.702 137.513,73.352 U14.C2@137.576,73.352
DDR_DQ21: U14.A3 U27.F19 | length 51.5
  Top Layer w0.09: U27.F19@100.001,76.802 100.301,76.502 101.015,76.502 101.275,76.762 101.905,76.762 101.945,76.802 102.204,76.802 102.244,76.842 121.779,76.842 123.709,74.913 125.306,74.913 125.445,75.052 125.445,75.25 125.076,75.619 125.076,76.986 125.162,77.072 125.331,77.072 125.421,76.982 125.421,76.426 125.771,76.075 128.339,76.075 128.464,75.95 130.267,75.95 130.58,75.638 134.176,75.638 134.468,75.345 134.791,75.345 135.132,75.004 135.132,74.681 135.576,74.237 135.576,73.177 135.801,72.952 136.251,72.952 136.376,72.827 136.376,72.061 136.123,71.809 135.675,71.809 135.414,71.548 135.414,71.225 136.101,70.538 136.101,70.298 136.197,70.202 136.452,70.202 136.573,70.323 136.573,71.324 136.687,71.438 138.79,71.438 139.021,71.67 139.021,72.142 139.135,72.256 139.135,72.51 U14.A3@139.175,72.55
DDR_DQ22: U14.C3 U27.E19 | length 51
  Top Layer w0.09: U27.E19@100.001,77.602 100.298,77.305 101.722,77.305 101.77,77.353 101.859,77.353 ; 101.86,77.352 102.906,77.352 ; 102.907,77.353 103.189,77.353 103.258,77.422 122.019,77.422 123.236,76.205 123.92,76.205 124.1,76.025 124.1,75.594 124.199,75.495 124.386,75.495 124.471,75.58 124.471,77.523 124.6,77.652 125.895,77.652 126.001,77.546 126.001,76.783 126.129,76.655 127.395,76.655 127.48,76.74 127.48,77.546 127.596,77.662 128.17,77.662 128.393,77.439 128.393,76.752 128.489,76.655 128.709,76.655 128.834,76.53 129.839,76.53 129.93,76.621 129.93,77.356 130.153,77.579 130.621,77.579 130.843,77.356 130.843,76.427 131.053,76.218 132.203,76.218 132.33,76.344 132.33,77.439 132.553,77.662 133.145,77.662 133.382,77.425 133.58,77.425 133.817,77.662 134.439,77.662 134.662,77.439 134.662,76.299 135.512,75.449 135.895,75.449 136.187,75.156 136.577,75.156 136.693,75.041 136.698,75.036 cw(c136.425,74.75) 136.711,75.023 136.716,75.018 136.798,74.935 136.825,74.909 136.825,74.588 136.851,74.561 137.154,74.258 137.154,74.082 137.512,73.725 137.688,73.725 137.92,73.493 137.92,72.895 U14.C3@137.575,72.55
DDR_DQ23: U14.A2 U27.E20 | length 50.1
  Top Layer w0.09: U27.E20@100.801,77.602 101.218,78.019 101.9,78.019 102.067,77.852 102.699,77.852 103.079,78.232 103.371,78.232 103.601,78.002 103.826,78.002 104.056,78.232 104.426,78.232 104.656,78.002 104.901,78.002 105.131,78.232 105.371,78.232 105.601,78.002 105.851,78.002 106.081,78.232 106.371,78.232 106.601,78.002 106.801,78.002 107.031,78.232 107.326,78.232 107.556,78.002 107.722,78.002 107.952,78.232 108.296,78.232 108.526,78.002 108.676,78.002 108.808,78.134 123.927,78.134 124.035,78.242 126.437,78.242 126.581,78.098 126.581,77.431 126.666,77.346 126.815,77.346 126.9,77.431 126.9,78.094 127.048,78.242 128.85,78.242 128.973,78.119 128.973,77.215 129.077,77.11 129.265,77.11 129.35,77.195 129.35,78.112 129.48,78.242 131.274,78.242 131.423,78.093 131.423,76.901 131.526,76.798 131.649,76.798 131.75,76.899 131.75,78.092 131.9,78.242 135.284,78.242 136.018,77.508 136.018,77.317 135.884,77.183 135.551,77.183 135.441,77.073 135.441,76.731 136.35,75.823 137.703,75.823 138.43,75.096 138.43,74.583 138.83,74.183 138.83,74.007 139.006,73.831 139.006,73.747 139.157,73.596 139.157,73.371 U14.A2@139.176,73.352
DDR_DQ24: U14.E3 U27.G19 | length 38.9
  Top Layer w0.09: U27.G19@100.001,76.002 100.007,75.995 100.285,75.995 100.576,75.704 102.757,75.704 102.779,75.682 121.299,75.682 123.23,73.751 124.897,73.751 126.648,72 126.707,71.94 130.827,71.94 131.183,71.584 133.566,71.584 133.976,71.993 133.976,72.666 134.237,72.927 135.365,72.927 135.729,72.563 135.964,72.563 U14.E3@135.976,72.552
DDR_DQ25: U14.H3 U27.G22 | length 34.1
  Top Layer w0.09: U27.G22@102.401,76.002 102.869,76.002 102.899,75.972 121.419,75.972 123.35,74.041 125.95,74.041 126.05,73.941 126.05,73.495 126.698,72.847 126.698,72.36 126.853,72.205 130.981,72.205 131.411,71.775 133.339,71.775 133.575,72.011 U14.H3@133.575,72.55
DDR_DQ26: U14.G2 U27.G21 | length 36.1
  Top Layer w0.09: U27.G21@101.601,76.002 101.925,76.002 102.218,76.295 102.986,76.295 103.019,76.262 121.539,76.262 123.47,74.331 125.831,74.331 126.025,74.525 126.025,75.259 126.261,75.495 128.099,75.495 128.483,75.111 128.659,75.111 128.918,75.37 129.995,75.37 130.32,75.045 133.191,75.045 133.43,74.806 133.43,74.736 133.661,74.505 133.708,74.505 133.983,74.229 133.983,73.799 134.375,73.407 U14.G2@134.375,73.35
DDR_DQ27: U14.F2 U27.G20 | length 37.7
  Top Layer w0.09: U27.G20@100.801,76.002 100.849,76.002 101.109,76.262 101.435,76.262 101.635,76.462 101.96,76.462 102.05,76.552 121.659,76.552 123.588,74.623 125.426,74.623 125.735,74.932 125.735,75.379 126.141,75.785 128.219,75.785 128.343,75.66 130.147,75.66 130.472,75.335 134.049,75.335 134.23,75.154 134.23,74.783 134.72,74.293 134.72,74.088 135.146,73.662 135.146,73.382 U14.F2@135.176,73.352
DDR_DQ28: U14.F7 U27.J21 | length 36
  Top Layer w0.09: U27.J21@101.6,74.4 101.762,74.562 120.835,74.562 122.766,72.631 124.433,72.631 126.244,70.82 130.345,70.82 130.442,70.723 133.348,70.723 133.734,70.336 134.562,70.336 135.176,69.723 U14.F7@135.176,69.352
DDR_DQ29: U14.F8 U27.J20 | length 37.2
  Top Layer w0.09: U27.J20@100.801,74.402 101.098,74.105 101.722,74.105 101.889,74.272 120.715,74.272 122.646,72.341 124.312,72.341 126.121,70.533 133.124,70.533 133.91,69.746 133.91,69.277 134.26,68.927 134.8,68.927 U14.F8@135.176,68.552
DDR_DQ30: U14.H7 U27.K20 | length 36.1
  Top Layer w0.09: U27.K20@100.801,73.602 100.859,73.602 101.072,73.815 101.842,73.815 102.009,73.982 120.594,73.982 122.526,72.051 124.192,72.051 124.457,71.786 124.457,71.65 124.3,71.492 124.3,71.227 124.385,71.143 124.943,71.143 125.028,71.058 125.028,70.498 125.155,70.372 125.337,70.372 125.487,70.521 125.722,70.521 126.041,70.203 129.388,70.203 129.516,70.331 132.902,70.331 133.559,69.673 133.559,69.365 U14.H7@133.575,69.35
DDR_DQ31: U14.H8 U27.L19 | length 36.7
  Top Layer w0.09: U27.L19@100.001,72.802 100.476,73.277 101.079,73.277 101.327,73.525 101.962,73.525 102.129,73.692 120.474,73.692 122.405,71.761 123.282,71.761 125.13,69.913 129.508,69.913 129.736,70.14 132.679,70.14 133.175,69.644 133.175,68.95 U14.H8@133.575,68.55
DDR_DQM0: U16.E7 U27.W21 | length 21.5
  Top Layer w0.09: U27.W21@101.601,66.402 101.629,66.374 101.859,66.374 102.17,66.685 102.593,66.685 104.673,64.605 104.956,64.605 106.005,63.556 107.809,61.752 108.351,61.752 110.558,63.96 115.258,63.96 115.429,64.13 118.495,64.13 U16.E7@119.5,63.125
DDR_DQM1: U16.D3 U27.P20 | length 34.2
  Top Layer w0.09: U27.P20@100.801,70.402 100.855,70.402 101.254,70.402 101.481,70.175 102.638,70.175 102.978,69.835 103.893,69.835 105.098,71.041 119.782,71.041 121.979,68.843 121.979,68.334 122.355,67.958 122.355,67.723 122.592,67.486 122.827,67.486 123.045,67.268 123.045,66.171 122.864,65.99 122.731,65.99 122.47,65.729 122.47,65.636 122.239,65.405 121.702,65.405 121.602,65.505 121.314,65.505 121.247,65.437 120.645,65.437 120.334,65.126 119.169,65.126 118.995,64.952 118.592,64.952 118.507,65.037 118.507,65.465 118.592,65.55 120.077,65.55 120.313,65.786 120.313,66.312 U16.D3@120.3,66.325
DDR_DQM2: U14.D3 U27.E21 | length 49.4
  Top Layer w0.09: U27.E21@101.603,77.603 102.927,77.603 103.036,77.712 124.035,77.712 124.275,77.952 126.168,77.952 126.291,77.829 126.291,77.141 126.376,77.056 127.1,77.056 127.19,77.146 127.19,77.834 127.308,77.952 128.494,77.952 128.683,77.764 128.683,77.095 128.957,76.82 129.526,76.82 129.64,76.935 129.64,77.695 129.814,77.869 130.938,77.869 131.133,77.674 131.133,76.73 131.356,76.508 131.817,76.508 132.04,76.73 132.04,77.771 132.221,77.952 134.994,77.952 135.139,77.806 135.139,76.623 136.23,75.533 137.001,75.533 137.63,74.904 137.63,74.586 137.938,74.278 137.938,74.112 138.298,73.752 138.461,73.752 138.73,73.483 138.73,72.344 138.115,71.729 137.599,71.729 U14.D3@136.776,72.552
DDR_DQM3: U14.E7 U27.H20 | length 37.6
  Top Layer w0.09: U27.H20@100.801,75.201 100.957,75.045 101.151,74.852 120.955,74.852 122.766,73.041 122.886,72.921 124.553,72.921 126.364,71.11 130.474,71.11 130.671,70.913 134.433,70.913 135.976,69.37 U14.E7@135.976,69.352
DDR_DQS0_N: U16.G3 U27.W20 | length 22.7
  Top Layer w0.09: U27.W20@100.801,66.402 101.101,66.702 101.554,66.702 101.827,66.975 102.727,66.975 104.741,64.961 105.025,64.961 107.746,62.24 108.414,62.24 111.151,64.977 111.505,64.977 112.085,64.397 112.476,64.397 112.942,64.863 113.318,64.863 113.751,64.43 117.453,64.43 117.901,64.878 U16.G3@117.901,66.327
DDR_DQS0_P: U16.F3 U27.V20 | length 23.8
  Top Layer w0.09: U27.V20@100.801,67.202 101.051,66.952 101.451,66.952 101.724,67.225 102.83,67.225 104.844,65.211 105.128,65.211 107.849,62.49 108.311,62.49 111.048,65.227 111.609,65.227 112.189,64.647 112.373,64.647 112.839,65.113 113.421,65.113 113.854,64.68 117.349,64.68 117.651,64.982 117.651,66.086 117.555,66.182 117.555,66.468 117.757,66.67 118.358,66.67 U16.F3@118.701,66.327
